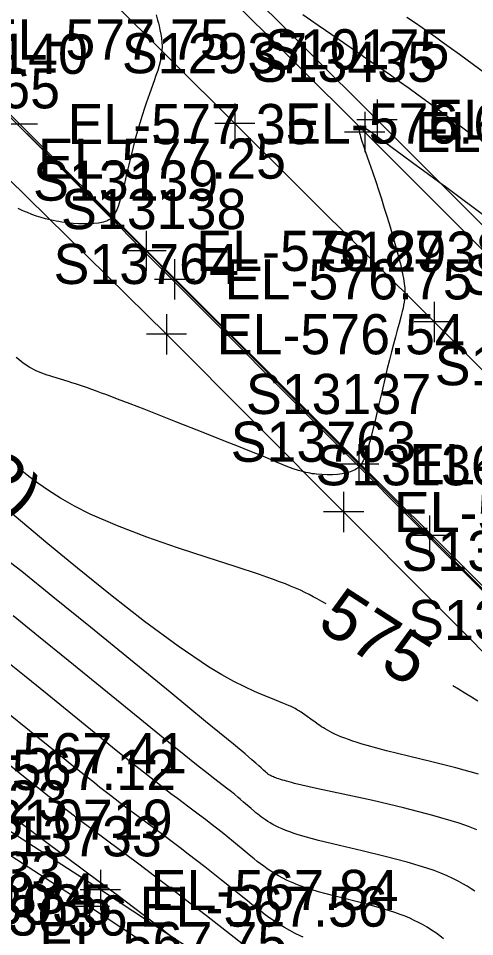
# Model space of a CAD drawing. Extents: x 1729869 to 1735532, y 648588 to 653771.
# Drawn here: x 1730822.3 to 1730867.7, y 652365.2 to 652456.6 of the extents above; entities that cross this region are included whole.
import ezdxf

# ---------------------------------------------------------------- set-up
doc = ezdxf.new("R2010")
doc.units = 0
for name, color, linetype in [('SURVEY - CENTERLINE - Preliminary', 7, 'Continuous'), ('SURVEY - CONTOURS - Index with Text', 7, 'Continuous'), ('SURVEY - CONTOURS - Intermediate with optional Text', 7, 'Continuous'), ('SURVEY - DRAINAGE - Area Shapes', 7, 'Continuous'), ('SURVEY - DTM - Breaklines', 7, 'Continuous'), ('SURVEY - DTM - Breaklines - Points - Elevations', 7, 'Continuous'), ('SURVEY - DTM - Breaklines - Points - Locators', 7, 'Continuous'), ('SURVEY - DTM - Breaklines - Points - Numbers', 7, 'Continuous'), ('SURVEY - TRANSPORTATION - Features', 7, 'Continuous'), ('SURVEY - TRANSPORTATION - Features - Points - Elevations', 7, 'Continuous'), ('SURVEY - TRANSPORTATION - Features - Points - Locators', 7, 'Continuous'), ('SURVEY - TRANSPORTATION - Features - Points - Numbers', 7, 'Continuous'), ('SURVEY - TRANSPORTATION - Roads', 7, 'Continuous'), ('SURVEY - TRANSPORTATION - Roads - Points - Elevations', 7, 'Continuous'), ('SURVEY - TRANSPORTATION - Roads - Points - Locators', 7, 'Continuous'), ('SURVEY - TRANSPORTATION - Roads - Points - Numbers', 7, 'Continuous'), ('SURVEY - UTILITIES - Poles and Miscellaneous with Text', 7, 'Continuous')]:
    doc.layers.add(name, color=color, linetype=linetype)

msp = doc.modelspace()

# ---------------------------------------------------------------- linework, layer by layer
at = {"layer": 'SURVEY - CENTERLINE - Preliminary'}
msp.add_line((1730712.736, 652555.602), (1731137.475, 652131.737), dxfattribs=at)
at = {"layer": 'SURVEY - CONTOURS - Index with Text'}
for points in [[(1730852.963, 652398.332), (1730852.556, 652398.574), (1730852.08, 652398.846), (1730851.693, 652399.057), (1730851.289, 652399.267), (1730850.864, 652399.478), (1730850.413, 652399.691), (1730849.929, 652399.907), (1730849.439, 652400.115), (1730848.91, 652400.329), (1730848.34, 652400.55), (1730847.723, 652400.779), (1730847.056, 652401.018), (1730846.334, 652401.268), (1730843.916, 652402.063), (1730841.144, 652402.953), (1730838.168, 652403.929), (1730835.135, 652404.982), (1730832.197, 652406.105), (1730829.502, 652407.288), (1730827.942, 652408.083), (1730826.55, 652408.877), (1730825.327, 652409.646), (1730824.273, 652410.367), (1730823.389, 652411.017), (1730822.677, 652411.572), (1730822.25, 652411.918)], [(1730868.069, 652388.652), (1730867.42, 652389.045), (1730866.773, 652389.443), (1730866.13, 652389.844), (1730865.565, 652390.198)], [(1730850.684, 652365.161), (1730850.435, 652365.269), (1730849.877, 652365.534), (1730849.342, 652365.814), (1730848.827, 652366.11), (1730848.329, 652366.418), (1730847.845, 652366.738), (1730847.372, 652367.067), (1730846.915, 652367.397), (1730846.464, 652367.734), (1730846.019, 652368.077), (1730845.578, 652368.422), (1730845.14, 652368.771), (1730842.567, 652370.835), (1730841.724, 652371.506), (1730840.89, 652372.161), (1730840.062, 652372.805), (1730839.248, 652373.431), (1730838.45, 652374.04), (1730837.662, 652374.636), (1730836.822, 652375.265), (1730834.132, 652377.262), (1730833.315, 652377.874), (1730832.439, 652378.539), (1730831.98, 652378.89), (1730831.499, 652379.261), (1730830.995, 652379.654), (1730830.463, 652380.07), (1730829.902, 652380.512), (1730829.31, 652380.982), (1730827.873, 652382.131), (1730826.321, 652383.384), (1730823.086, 652386.003), (1730821.513, 652387.273)]]:
    msp.add_lwpolyline(points, dxfattribs=at)
at = {"layer": 'SURVEY - CONTOURS - Intermediate with optional Text'}
for points in [[(1730836.048, 652456.991), (1730836.2, 652456.442), (1730836.271, 652456.17), (1730836.339, 652455.899), (1730836.434, 652455.489), (1730836.515, 652455.079), (1730836.579, 652454.668), (1730836.621, 652454.254), (1730836.638, 652453.837), (1730836.623, 652453.415), (1730836.568, 652452.937), (1730836.476, 652452.451), (1730836.352, 652451.957), (1730836.204, 652451.455), (1730836.036, 652450.945), (1730835.856, 652450.426), (1730835.388, 652449.11), (1730835.228, 652448.654), (1730835.066, 652448.185), (1730834.904, 652447.704), (1730834.667, 652446.974), (1730834.433, 652446.217), (1730834.203, 652445.438), (1730833.98, 652444.64), (1730833.764, 652443.828), (1730833.558, 652443.006), (1730833.333, 652442.051), (1730833.118, 652441.11), (1730832.908, 652440.204), (1730832.699, 652439.354), (1730832.486, 652438.582), (1730832.265, 652437.911), (1730832.197, 652437.736), (1730832.128, 652437.571), (1730832.056, 652437.417), (1730831.997, 652437.301), (1730831.935, 652437.192), (1730831.872, 652437.09), (1730831.805, 652436.995), (1730831.735, 652436.907), (1730831.662, 652436.826), (1730831.601, 652436.767), (1730831.538, 652436.712), (1730831.473, 652436.66), (1730831.405, 652436.613), (1730831.334, 652436.568), (1730831.261, 652436.527), (1730831.123, 652436.461), (1730830.976, 652436.403), (1730830.822, 652436.353), (1730830.659, 652436.312), (1730830.489, 652436.276), (1730830.311, 652436.247), (1730829.864, 652436.197), (1730829.382, 652436.172), (1730828.874, 652436.171), (1730828.347, 652436.189), (1730827.809, 652436.226), (1730827.266, 652436.279), (1730826.971, 652436.313), (1730826.676, 652436.352), (1730826.382, 652436.397), (1730826.089, 652436.447), (1730825.796, 652436.503), (1730825.504, 652436.565), (1730825.049, 652436.677), (1730824.596, 652436.806), (1730824.144, 652436.952), (1730823.693, 652437.114), (1730823.244, 652437.293), (1730822.797, 652437.487), (1730822.324, 652437.712)], [(1730867.878, 652444.73), (1730863.438, 652448.021), (1730862.136, 652448.979), (1730861.228, 652449.641), (1730860.273, 652450.326), (1730859.369, 652450.967), (1730858.459, 652451.605), (1730857.422, 652452.324), (1730854.274, 652454.489), (1730852.17, 652455.942), (1730850.651, 652456.999)], [(1730871.536, 652449.134), (1730866.224, 652453.041), (1730865.216, 652453.775), (1730864.53, 652454.269), (1730863.846, 652454.757), (1730863.181, 652455.225), (1730862.516, 652455.686), (1730861.746, 652456.211), (1730860.985, 652456.722)], [(1730870.078, 652435.962), (1730865.914, 652439.067), (1730864.854, 652439.851), (1730864.416, 652440.173), (1730863.404, 652440.913), (1730861.71, 652442.151), (1730860.549, 652443.007), (1730858.417, 652444.59), (1730857.765, 652445.068), (1730857.399, 652445.331), (1730857.232, 652445.447), (1730857.078, 652445.552), (1730856.935, 652445.645), (1730856.791, 652445.733), (1730856.724, 652445.771), (1730856.662, 652445.804), (1730856.603, 652445.833), (1730856.549, 652445.856), (1730856.485, 652445.879), (1730856.428, 652445.894), (1730856.377, 652445.898), (1730856.334, 652445.893), (1730856.299, 652445.877), (1730856.271, 652445.85), (1730856.248, 652445.804), (1730856.234, 652445.743), (1730856.231, 652445.667), (1730856.235, 652445.577), (1730856.248, 652445.474), (1730856.269, 652445.359), (1730856.302, 652445.205), (1730856.345, 652445.035), (1730856.395, 652444.85), (1730856.524, 652444.42), (1730856.679, 652443.938), (1730856.855, 652443.416), (1730857.244, 652442.295), (1730857.57, 652441.356), (1730857.935, 652440.284), (1730858.171, 652439.576), (1730858.471, 652438.654), (1730858.76, 652437.741), (1730859.04, 652436.835), (1730859.326, 652435.882), (1730859.603, 652434.935), (1730859.871, 652433.995), (1730860.039, 652433.397), (1730860.2, 652432.799), (1730860.278, 652432.5), (1730860.354, 652432.199), (1730860.472, 652431.705), (1730860.578, 652431.212), (1730860.668, 652430.723), (1730860.738, 652430.241), (1730860.784, 652429.771), (1730860.8, 652429.316), (1730860.793, 652428.999), (1730860.77, 652428.689), (1730860.732, 652428.383), (1730860.682, 652428.078), (1730860.621, 652427.771), (1730860.551, 652427.459), (1730860.481, 652427.173), (1730860.405, 652426.879), (1730860.238, 652426.262), (1730860.052, 652425.593), (1730859.869, 652424.927), (1730859.677, 652424.209), (1730859.475, 652423.443), (1730859.267, 652422.631), (1730859.055, 652421.775), (1730858.838, 652420.878), (1730858.534, 652419.568), (1730858.228, 652418.23), (1730857.923, 652416.912), (1730857.62, 652415.659), (1730857.322, 652414.521), (1730857.029, 652413.544), (1730856.978, 652413.39), (1730856.927, 652413.243), (1730856.875, 652413.103), (1730856.824, 652412.969), (1730856.772, 652412.842), (1730856.711, 652412.703), (1730856.656, 652412.587), (1730856.6, 652412.479), (1730856.542, 652412.377), (1730856.483, 652412.281), (1730856.421, 652412.193), (1730856.357, 652412.11), (1730856.307, 652412.053), (1730856.256, 652411.999), (1730856.203, 652411.948), (1730856.149, 652411.9), (1730856.092, 652411.854), (1730856, 652411.787), (1730855.855, 652411.698), (1730855.701, 652411.618), (1730855.536, 652411.548), (1730855.362, 652411.485), (1730855.178, 652411.43), (1730854.986, 652411.381), (1730854.553, 652411.296), (1730854.087, 652411.236), (1730853.593, 652411.2), (1730853.08, 652411.19), (1730852.551, 652411.207), (1730852.015, 652411.251), (1730851.805, 652411.276), (1730851.594, 652411.305), (1730851.382, 652411.34), (1730851.169, 652411.38), (1730850.956, 652411.425), (1730850.741, 652411.476), (1730850.222, 652411.622), (1730849.693, 652411.798), (1730849.153, 652411.999), (1730848.599, 652412.22), (1730848.031, 652412.455), (1730847.447, 652412.701), (1730846.724, 652413.002), (1730845.978, 652413.309), (1730845.21, 652413.622), (1730844.422, 652413.94), (1730842.799, 652414.59), (1730840.894, 652415.346), (1730838.028, 652416.474), (1730834.857, 652417.715), (1730833.455, 652418.26), (1730832.223, 652418.733), (1730831.146, 652419.14), (1730830.63, 652419.331), (1730830.128, 652419.515), (1730829.641, 652419.689), (1730829.223, 652419.836), (1730828.816, 652419.976), (1730828.42, 652420.11), (1730828.033, 652420.238), (1730827.656, 652420.359), (1730827.289, 652420.475), (1730825.757, 652420.946), (1730825.466, 652421.039), (1730825.207, 652421.124), (1730824.95, 652421.213), (1730824.693, 652421.308), (1730824.436, 652421.41), (1730824.178, 652421.523), (1730823.917, 652421.647), (1730823.677, 652421.773), (1730823.432, 652421.912), (1730823.181, 652422.068), (1730822.924, 652422.243), (1730822.658, 652422.439), (1730822.382, 652422.659), (1730822.121, 652422.883)], [(1730868.127, 652381.392), (1730865.859, 652382.026), (1730863.495, 652382.624), (1730861.159, 652383.191), (1730858.971, 652383.727), (1730857.056, 652384.234), (1730856.539, 652384.385), (1730856.058, 652384.534), (1730855.611, 652384.681), (1730855.197, 652384.825), (1730854.814, 652384.967), (1730854.438, 652385.116), (1730854.127, 652385.249), (1730853.84, 652385.379), (1730853.574, 652385.508), (1730853.327, 652385.636), (1730853.097, 652385.761), (1730852.882, 652385.885), (1730852.691, 652386.001), (1730852.51, 652386.115), (1730852.339, 652386.227), (1730852.175, 652386.338), (1730851.868, 652386.555), (1730851.462, 652386.852), (1730851.08, 652387.134), (1730850.843, 652387.304), (1730850.606, 652387.468), (1730850.487, 652387.548), (1730850.366, 652387.626), (1730850.249, 652387.699), (1730850.13, 652387.77), (1730850.008, 652387.841), (1730849.883, 652387.91), (1730849.754, 652387.979), (1730849.552, 652388.08), (1730849.419, 652388.143), (1730849.28, 652388.207), (1730848.981, 652388.336), (1730848.648, 652388.473), (1730847.456, 652388.945), (1730846.713, 652389.248), (1730845.855, 652389.619), (1730844.882, 652390.073), (1730843.795, 652390.626), (1730842.593, 652391.292), (1730841.276, 652392.086), (1730838.228, 652394.141), (1730834.898, 652396.6), (1730831.494, 652399.255), (1730828.222, 652401.898), (1730825.289, 652404.322), (1730821.281, 652407.675)], [(1730867.965, 652375.845), (1730867.122, 652376.175), (1730866.192, 652376.504), (1730863.594, 652377.288), (1730860.661, 652378.042), (1730857.61, 652378.751), (1730854.656, 652379.4), (1730852.015, 652379.975), (1730849.837, 652380.475), (1730849.537, 652380.55), (1730849.278, 652380.617), (1730849.039, 652380.682), (1730848.819, 652380.744), (1730848.616, 652380.803), (1730848.43, 652380.86), (1730848.26, 652380.915), (1730848.108, 652380.966), (1730847.969, 652381.016), (1730847.842, 652381.065), (1730847.728, 652381.111), (1730847.624, 652381.156), (1730847.53, 652381.2), (1730847.445, 652381.242), (1730847.369, 652381.284), (1730847.299, 652381.324), (1730847.235, 652381.364), (1730847.176, 652381.404), (1730847.121, 652381.444), (1730847.021, 652381.523), (1730846.928, 652381.605), (1730846.74, 652381.786), (1730846.497, 652382.02), (1730846.267, 652382.231), (1730845.965, 652382.498), (1730845.579, 652382.83), (1730844.897, 652383.404), (1730843.743, 652384.364), (1730840.975, 652386.647), (1730837.449, 652389.539), (1730833.51, 652392.758), (1730829.505, 652396.021), (1730825.776, 652399.046), (1730822.67, 652401.55), (1730821.556, 652402.441)], [(1730867.757, 652369.726), (1730867.39, 652369.977), (1730867.001, 652370.227), (1730866.584, 652370.476), (1730866.099, 652370.744), (1730865.573, 652371.01), (1730865.005, 652371.273), (1730864.389, 652371.533), (1730863.722, 652371.79), (1730862.999, 652372.043), (1730861.03, 652372.636), (1730858.841, 652373.206), (1730856.559, 652373.753), (1730854.309, 652374.281), (1730852.219, 652374.793), (1730850.413, 652375.29), (1730850.094, 652375.389), (1730849.791, 652375.487), (1730849.354, 652375.64), (1730848.954, 652375.791), (1730848.587, 652375.942), (1730848.25, 652376.093), (1730847.941, 652376.243), (1730847.657, 652376.392), (1730847.398, 652376.539), (1730847.158, 652376.685), (1730846.934, 652376.831), (1730846.724, 652376.977), (1730846.526, 652377.121), (1730846.337, 652377.265), (1730846.16, 652377.406), (1730845.989, 652377.546), (1730845.824, 652377.685), (1730845.505, 652377.96), (1730844.755, 652378.616), (1730844.461, 652378.868), (1730844.17, 652379.112), (1730843.875, 652379.354), (1730843.545, 652379.618), (1730843.069, 652379.989), (1730841.883, 652380.903), (1730841.08, 652381.531), (1730840.078, 652382.323), (1730838.828, 652383.325), (1730836.414, 652385.278), (1730833.546, 652387.613), (1730827.303, 652392.708), (1730824.357, 652395.104), (1730821.815, 652397.159)], [(1730864.649, 652365.003), (1730864.274, 652365.293), (1730863.881, 652365.579), (1730863.467, 652365.861), (1730863.029, 652366.139), (1730862.562, 652366.41), (1730862.164, 652366.623), (1730861.742, 652366.832), (1730861.297, 652367.036), (1730860.825, 652367.234), (1730860.326, 652367.428), (1730859.797, 652367.617), (1730858.397, 652368.055), (1730856.876, 652368.471), (1730853.726, 652369.278), (1730852.225, 652369.685), (1730850.858, 652370.107), (1730850.479, 652370.24), (1730850.117, 652370.374), (1730849.591, 652370.588), (1730849.104, 652370.808), (1730848.65, 652371.034), (1730848.227, 652371.264), (1730847.828, 652371.498), (1730847.451, 652371.737), (1730847.098, 652371.975), (1730846.759, 652372.216), (1730846.432, 652372.459), (1730846.114, 652372.703), (1730845.805, 652372.949), (1730845.5, 652373.196), (1730844.911, 652373.682), (1730843.752, 652374.646), (1730843.184, 652375.111), (1730842.619, 652375.567), (1730842.056, 652376.014), (1730841.507, 652376.443), (1730840.963, 652376.862), (1730840.377, 652377.306), (1730839.312, 652378.101), (1730838.169, 652378.955), (1730837.528, 652379.439), (1730836.81, 652379.99), (1730836.005, 652380.616), (1730835.084, 652381.341), (1730834.027, 652382.184), (1730832.086, 652383.748), (1730829.887, 652385.533), (1730825.204, 652389.346), (1730822.965, 652391.163), (1730820.957, 652392.781)], [(1730845.054, 652364.16), (1730841.064, 652367.267), (1730839.407, 652368.55), (1730837.783, 652369.8), (1730836.201, 652371.008), (1730835.166, 652371.793), (1730834.05, 652372.634), (1730832.548, 652373.755), (1730829.554, 652375.98), (1730828.534, 652376.744), (1730827.491, 652377.532), (1730826.959, 652377.939), (1730826.415, 652378.356), (1730825.858, 652378.787), (1730825.287, 652379.231), (1730824.699, 652379.692), (1730823.782, 652380.417), (1730822.837, 652381.17), (1730819.96, 652383.467)], [(1730837.801, 652365.013), (1730837.553, 652365.214), (1730837.165, 652365.526), (1730836.752, 652365.853), (1730836.315, 652366.194), (1730835.857, 652366.547), (1730834.89, 652367.288), (1730833.672, 652368.212), (1730832.405, 652369.167), (1730831.001, 652370.219), (1730829.098, 652371.638), (1730824.78, 652374.846), (1730823.019, 652376.163), (1730821.888, 652377.015)]]:
    msp.add_lwpolyline(points, dxfattribs=at)
at = {"layer": 'SURVEY - DRAINAGE - Area Shapes'}
msp.add_lwpolyline([(1731097.142, 652171.409), (1731011.148, 652256.97), (1730865.03, 652403.158), (1730749.606, 652518.939), (1730781.764, 652550.883), (1730851.291, 652571.58), (1730949.072, 652515.98), (1730982.838, 652438.563), (1731020.351, 652368.14), (1731165.291, 652192.393), (1731281.807, 652137.032), (1731316.797, 652088.672), (1731252.279, 652032.718), (1731179.777, 652109.245)], close=True, dxfattribs=at)
at = {"layer": 'SURVEY - DTM - Breaklines'}
for points in [[(1730587.774, 652756.33), (1730594.925, 652741.91), (1730609.577, 652716.644), (1730625.689, 652692.371), (1730643.455, 652668.78), (1730662.354, 652646.079), (1730682.257, 652624.222), (1730702.707, 652602.668), (1730723.576, 652581.257), (1730744.651, 652559.957), (1730765.85, 652538.806), (1730769.397, 652535.272), (1730794.44, 652510.116), (1730815.612, 652488.907), (1730836.832, 652467.723), (1730858.033, 652446.55), (1730879.263, 652425.34), (1730900.421, 652404.063), (1730921.638, 652382.868), (1730942.829, 652361.634), (1730964.104, 652340.505), (1730985.371, 652319.345), (1731006.623, 652298.196)], [(1731001.804, 652246.837), (1730986.97, 652258.675), (1730981.863, 652262.82), (1730979.27, 652264.774), (1730974.15, 652268.679), (1730954.012, 652283.621), (1730933.622, 652298.476), (1730913.393, 652313.326), (1730892.983, 652327.762), (1730872.274, 652341.974), (1730851.38, 652356.104), (1730830.504, 652369.859), (1730809.435, 652383.476), (1730788.147, 652396.932), (1730766.91, 652410.117), (1730745.474, 652423.147), (1730723.671, 652435.774), (1730701.831, 652448.311), (1730680.069, 652460.611)]]:
    msp.add_lwpolyline(points, dxfattribs=at)
at = {"layer": 'SURVEY - DTM - Breaklines - Points - Locators'}
for p, q in [((1730858.033, 652448.55), (1730858.033, 652444.55)), ((1730860.033, 652446.55), (1730856.033, 652446.55)), ((1730830.504, 652371.859), (1730830.504, 652367.859)), ((1730832.504, 652369.859), (1730828.504, 652369.859))]:
    msp.add_line(p, q, dxfattribs=at)
at = {"layer": 'SURVEY - TRANSPORTATION - Features'}
for points in [[(1730835.6, 652466.493), (1730856.805, 652445.317), (1730878.032, 652424.109), (1730899.189, 652402.834), (1730920.407, 652381.638), (1730941.598, 652360.404), (1730962.875, 652339.272), (1730984.142, 652318.113), (1731005.396, 652296.96), (1731008.075, 652296.352)], [(1731047.725, 652209.413), (1731050.352, 652211.959), (1731031.534, 652230.733), (1731013.814, 652248.346), (1730996.168, 652266.058), (1730978.494, 652283.764), (1730960.753, 652301.374), (1730943.107, 652319.11), (1730925.408, 652336.717), (1730907.681, 652354.359), (1730890.139, 652372.168), (1730872.363, 652389.742), (1730854.712, 652407.49), (1730837.083, 652425.187), (1730819.286, 652442.675), (1730801.527, 652460.322)], [(1730679.148, 652458.959), (1730700.909, 652446.658), (1730722.72, 652434.139), (1730744.445, 652421.455), (1730765.867, 652408.433), (1730787.104, 652395.248), (1730808.362, 652381.812), (1730829.417, 652368.203), (1730850.292, 652354.449), (1730871.15, 652340.343), (1730891.852, 652326.16), (1730912.257, 652311.717), (1730932.625, 652297.091), (1730952.92, 652282.174), (1730972.943, 652267.104), (1730977.983, 652263.095), (1730980.577, 652261.164), (1730985.786, 652257.149), (1731000.693, 652245.44)]]:
    msp.add_lwpolyline(points, dxfattribs=at)
at = {"layer": 'SURVEY - TRANSPORTATION - Features - Points - Locators'}
for p, q in [((1730856.805, 652447.317), (1730856.805, 652443.317)), ((1730858.805, 652445.317), (1730854.805, 652445.317)), ((1730837.083, 652427.187), (1730837.083, 652423.187)), ((1730839.083, 652425.187), (1730835.083, 652425.187)), ((1730854.712, 652409.49), (1730854.712, 652405.49)), ((1730856.712, 652407.49), (1730852.712, 652407.49)), ((1730829.417, 652370.203), (1730829.417, 652366.203)), ((1730831.417, 652368.203), (1730827.417, 652368.203))]:
    msp.add_line(p, q, dxfattribs=at)
at = {"layer": 'SURVEY - TRANSPORTATION - Roads'}
for points in [[(1730831.15, 652458.88), (1730843.882, 652446.168), (1730863.714, 652426.414), (1730875.025, 652415.105), (1730899.039, 652391.043), (1730910.369, 652379.748), (1730935.764, 652354.333), (1730956.03, 652334.21), (1730971.982, 652318.295), (1730987.466, 652302.848), (1731007.326, 652283.108), (1731032.831, 652257.697), (1731045.572, 652244.982), (1731076.702, 652213.886), (1731092.244, 652198.318)], [(1731097.861, 652171.053), (1731071.042, 652197.973), (1731062.56, 652206.46), (1731042.759, 652226.258), (1731034.268, 652234.739), (1731025.766, 652243.207), (1731017.244, 652251.657), (1730998.779, 652269.963), (1730976.367, 652292.329), (1730961.856, 652306.785), (1730957.876, 652310.753), (1730953.651, 652315.013), (1730930.881, 652337.876), (1730922.712, 652345.955), (1730897.696, 652370.816), (1730890.153, 652378.304), (1730871.708, 652396.621), (1730863.262, 652405.143), (1730856.224, 652412.244), (1730837.876, 652430.653), (1730835.053, 652433.485), (1730822.235, 652446.112)]]:
    msp.add_lwpolyline(points, dxfattribs=at)
at = {"layer": 'SURVEY - TRANSPORTATION - Roads - Points - Locators'}
for p, q in [((1730843.882, 652448.168), (1730843.882, 652444.168)), ((1730824.235, 652446.112), (1730820.235, 652446.112)), ((1730845.882, 652446.168), (1730841.882, 652446.168)), ((1730835.053, 652435.485), (1730835.053, 652431.485)), ((1730837.053, 652433.485), (1730833.053, 652433.485)), ((1730837.876, 652432.653), (1730837.876, 652428.653)), ((1730839.876, 652430.653), (1730835.876, 652430.653)), ((1730863.714, 652428.414), (1730863.714, 652424.414)), ((1730865.714, 652426.414), (1730861.714, 652426.414)), ((1730856.224, 652414.244), (1730856.224, 652410.244)), ((1730858.224, 652412.244), (1730854.224, 652412.244)), ((1730863.262, 652407.143), (1730863.262, 652403.143)), ((1730865.262, 652405.143), (1730861.262, 652405.143))]:
    msp.add_line(p, q, dxfattribs=at)

# ---------------------------------------------------------------- texts
at = {"layer": 'SURVEY - CONTOURS - Index with Text'}
msp.add_text('575', height=5, rotation=327.16236, dxfattribs=at).set_placement((1730851.914, 652396.018))
at = {"layer": 'SURVEY - DTM - Breaklines - Points - Elevations'}
for s, p in [('EL-576.23', (1730863.033, 652444.55)), ('EL-567.41', (1730814.435, 652381.476)), ('EL-567.84', (1730835.504, 652367.859))]:
    msp.add_text(s, height=4, dxfattribs=at).set_placement(p)
at = {"layer": 'SURVEY - DTM - Breaklines - Points - Numbers'}
for s, p in [('S10175', (1730846.793, 652451.55)), ('S10719', (1730819.249, 652374.859))]:
    msp.add_text(s, height=4, dxfattribs=at).set_placement(p)
at = {"layer": 'SURVEY - TRANSPORTATION - Features - Points - Elevations'}
for s, p in [('EL-575.98', (1730861.805, 652443.317)), ('EL-577.25', (1730824.286, 652440.675)), ('EL-576.54', (1730842.083, 652423.187)), ('EL-575.84', (1730859.712, 652405.49)), ('EL-567.12', (1730813.362, 652379.812)), ('EL-567.56', (1730834.417, 652366.203))]:
    msp.add_text(s, height=4, dxfattribs=at).set_placement(p)
at = {"layer": 'SURVEY - TRANSPORTATION - Features - Points - Numbers'}
for s, p in [('S13435', (1730845.565, 652450.317)), ('S13765', (1730808.046, 652447.675)), ('S13764', (1730825.843, 652430.187)), ('S13436', (1730866.682, 652429.109)), ('S13763', (1730843.472, 652412.49)), ('S13762', (1730861.123, 652394.742)), ('S13733', (1730818.177, 652373.203))]:
    msp.add_text(s, height=4, dxfattribs=at).set_placement(p)
at = {"layer": 'SURVEY - TRANSPORTATION - Roads - Points - Elevations'}
for s, p in [('EL-577.75', (1730818.691, 652452.532)), ('EL-577.35', (1730827.235, 652444.112)), ('EL-576.69', (1730848.882, 652444.168)), ('EL-576.87', (1730840.053, 652431.485)), ('EL-576.75', (1730842.876, 652428.653)), ('EL-576.00', (1730861.224, 652410.244)), ('EL-567.23', (1730802.557, 652376.752)), ('EL-567.75', (1730824.407, 652362.667))]:
    msp.add_text(s, height=4, dxfattribs=at).set_placement(p)
at = {"layer": 'SURVEY - TRANSPORTATION - Roads - Points - Numbers'}
for s, p in [('S13140', (1730810.822, 652451.112)), ('S12937', (1730832.642, 652451.168)), ('S13139', (1730823.798, 652438.485)), ('S13138', (1730826.589, 652435.653)), ('S12938', (1730852.427, 652431.414)), ('S12939', (1730863.77, 652420.105)), ('S13137', (1730844.984, 652417.244)), ('S13136', (1730851.912, 652410.143)), ('S13135', (1730860.468, 652401.621)), ('S13033', (1730808.167, 652369.667)), ('S13034', (1730811.529, 652367.499)), ('S13035', (1730813.209, 652366.415)), ('S13036', (1730814.771, 652365.318))]:
    msp.add_text(s, height=4, dxfattribs=at).set_placement(p)
at = {"layer": 'SURVEY - UTILITIES - Poles and Miscellaneous with Text'}
msp.add_text('TDOT ITS (2)', height=5, rotation=315.23335, dxfattribs=at).set_placement((1730792.928, 652434.8))

doc.saveas('drawing.dxf')
